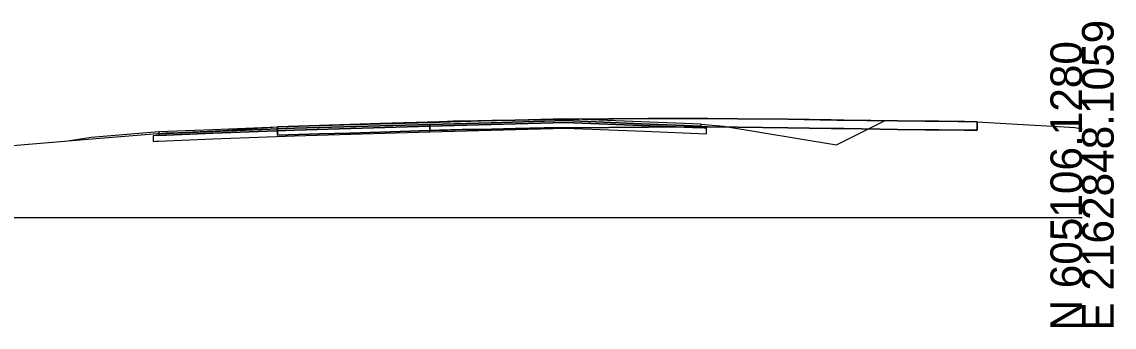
# Model space of a CAD drawing. Extents: x -26 to 1303, y -10 to 12038.
# Drawn here: x 206.1 to 302.8, y 9990.3 to 10017.3 of the extents above; entities that cross this region are included whole.
import ezdxf

# ---------------------------------------------------------------- set-up
doc = ezdxf.new("R2010")
doc.units = 0
for name, color, linetype in [('RD_GPK_XS_Cell', 7, 'Continuous'), ('RD_XS_Base', 7, 'Continuous'), ('RD_XS_ExGround', 7, 'Continuous'), ('RD_XS_ExPaveRet', 7, 'Continuous'), ('RD_XS_Greenside', 7, 'Continuous'), ('RD_XS_Pave', 7, 'Continuous'), ('RD_XS_PaveOvlay_CP', 7, 'Continuous'), ('RD_XS_TieSlope', 7, 'Continuous')]:
    doc.layers.add(name, color=color, linetype=linetype)

msp = doc.modelspace()

# ---------------------------------------------------------------- linework, layer by layer
at = {"layer": 'RD_GPK_XS_Cell'}
msp.add_line((150, 10000), (300, 10000), dxfattribs=at)
at = {"layer": 'RD_XS_Base'}
for p, q in [((242.262, 10008.146), (242.262, 10008.232)), ((242.262, 10008.232), (242.262, 10007.874)), ((247.684, 10008.225), (242.262, 10008.073)), ((242.262, 10008.073), (242.262, 10008.146)), ((254.263, 10008.41), (247.684, 10008.225)), ((260.954, 10008.142), (254.263, 10008.41)), ((266.263, 10007.93), (260.954, 10008.142)), ((218.003, 10007.246), (217.762, 10007.236)), ((217.762, 10007.236), (217.762, 10006.978)), ((218.262, 10007.256), (218.003, 10007.246)), ((223.047, 10007.448), (218.262, 10007.256)), ((230.262, 10007.737), (223.047, 10007.448)), ((223.047, 10006.948), (230.262, 10007.237)), ((242.262, 10008.073), (230.262, 10007.737)), ((230.262, 10007.237), (242.262, 10007.573)), ((242.262, 10008.073), (242.262, 10008.073)), ((242.262, 10008.073), (242.262, 10008.073)), ((242.262, 10007.801), (242.262, 10008.073)), ((242.262, 10007.874), (242.262, 10007.573)), ((242.262, 10007.573), (242.262, 10007.801)), ((242.262, 10007.573), (247.684, 10007.725)), ((247.684, 10007.725), (254.263, 10007.91)), ((254.263, 10007.91), (261.235, 10007.631)), ((261.235, 10007.631), (266.763, 10007.41)), ((266.544, 10007.919), (266.263, 10007.93)), ((266.763, 10007.91), (266.544, 10007.919)), ((266.763, 10007.629), (266.763, 10007.91)), ((266.763, 10007.41), (266.763, 10007.629)), ((217.762, 10006.978), (217.762, 10006.736)), ((217.762, 10006.736), (218.003, 10006.746)), ((218.003, 10006.746), (218.262, 10006.756)), ((218.262, 10006.756), (223.047, 10006.948))]:
    msp.add_line(p, q, dxfattribs=at)
at = {"layer": 'RD_XS_ExGround'}
msp.add_lwpolyline([(203.207, 10006.202), (207.088, 10006.507), (213.078, 10007.006), (218.879, 10007.501), (219.307, 10007.493), (223.898, 10007.688), (228.782, 10008.031), (232.493, 10008.146), (237.9, 10008.309), (243.81, 10008.49), (244.316, 10008.515), (244.522, 10008.52), (244.93, 10008.523), (245.804, 10008.523), (246.76, 10008.548), (252.362, 10008.677), (261.593, 10008.753), (266.863, 10008.772), (273.943, 10008.687), (278.287, 10008.621), (283.667, 10008.546), (287.328, 10008.51), (290.699, 10008.479), (294.248, 10008.249), (298.417, 10008.024), (299.355, 10007.972), (300, 10007.845)], dxfattribs=at)
at = {"layer": 'RD_XS_ExPaveRet'}
for points in [[(290.699, 10008.479), (290.7, 10008.479), (290.7, 10008.148), (290.7, 10007.729), (290.699, 10007.729), (290.699, 10007.729), (289.583, 10007.739), (287.328, 10007.76), (286.097, 10007.772), (283.667, 10007.796), (278.934, 10007.862), (278.287, 10007.871), (277.776, 10007.879), (273.943, 10007.937), (269.502, 10007.99), (266.863, 10008.022), (264.839, 10008.014), (261.593, 10008.003), (254.6, 10007.946), (252.362, 10007.927), (249.814, 10007.868), (247.742, 10007.82), (246.494, 10007.789), (245.838, 10007.774), (245.475, 10007.774), (245.118, 10007.774), (244.496, 10007.77), (244.414, 10007.767), (244.316, 10007.765), (244.074, 10007.753), (243.81, 10007.74), (243.073, 10007.717), (237.9, 10007.559), (235.183, 10007.477), (232.493, 10007.396), (230.658, 10007.339), (228.782, 10007.281), (228.782, 10007.771), (228.782, 10008.031), (230.658, 10008.089), (232.493, 10008.146), (235.183, 10008.227), (237.9, 10008.309), (243.073, 10008.467), (243.81, 10008.49), (244.074, 10008.503), (244.316, 10008.515), (244.414, 10008.517), (244.496, 10008.52), (245.118, 10008.524), (245.475, 10008.524), (245.838, 10008.524), (246.494, 10008.539), (247.742, 10008.57), (249.814, 10008.618), (252.362, 10008.677), (254.6, 10008.696), (261.593, 10008.753), (264.839, 10008.764), (266.863, 10008.772), (269.502, 10008.74), (273.943, 10008.687), (277.776, 10008.629), (278.287, 10008.621), (278.934, 10008.612), (283.667, 10008.546), (286.097, 10008.522), (287.328, 10008.51), (289.583, 10008.489), (290.699, 10008.479), (290.699, 10008.479)], [(290.699, 10008.479), (289.583, 10008.489), (287.328, 10008.51), (286.097, 10008.522), (283.667, 10008.546), (278.934, 10008.612), (278.287, 10008.621), (277.776, 10008.629), (273.943, 10008.687), (269.502, 10008.74), (266.863, 10008.772), (264.839, 10008.764), (261.593, 10008.753), (254.6, 10008.696), (252.362, 10008.677), (249.814, 10008.618), (247.742, 10008.57), (246.494, 10008.539), (245.838, 10008.524), (245.475, 10008.524), (245.118, 10008.524), (244.496, 10008.52), (244.414, 10008.517), (244.316, 10008.515), (244.074, 10008.503), (243.81, 10008.49), (243.073, 10008.467), (237.9, 10008.309), (235.183, 10008.227), (232.493, 10008.146), (230.658, 10008.089), (228.782, 10008.031), (228.782, 10007.771), (228.782, 10007.281), (230.658, 10007.339), (232.493, 10007.396), (235.183, 10007.477), (237.9, 10007.559), (243.073, 10007.717), (243.81, 10007.74), (244.074, 10007.753), (244.316, 10007.765), (244.414, 10007.767), (244.496, 10007.77), (245.118, 10007.774), (245.475, 10007.774), (245.838, 10007.774), (246.494, 10007.789), (247.742, 10007.82), (249.814, 10007.868), (252.362, 10007.927), (254.6, 10007.946), (261.593, 10008.003), (264.839, 10008.014), (266.863, 10008.022), (269.502, 10007.99), (273.943, 10007.937), (277.776, 10007.879), (278.287, 10007.871), (278.934, 10007.862), (283.667, 10007.796), (286.097, 10007.772), (287.328, 10007.76), (289.583, 10007.739), (290.699, 10007.729), (290.7, 10007.729), (290.7, 10008.148), (290.699, 10008.479), (290.699, 10008.479)]]:
    msp.add_lwpolyline(points, dxfattribs=at)
at = {"layer": 'RD_XS_Greenside'}
for p, q in [((278.264, 10006.422), (282.562, 10008.571)), ((268.263, 10008.088), (278.264, 10006.422)), ((212.262, 10007.094), (210.392, 10006.782))]:
    msp.add_line(p, q, dxfattribs=at)
at = {"layer": 'RD_XS_Pave'}
for p, q in [((242.262, 10008.391), (230.262, 10008.055)), ((242.262, 10008.232), (230.262, 10007.896)), ((230.262, 10007.896), (242.262, 10008.232)), ((247.684, 10008.543), (242.262, 10008.391)), ((247.684, 10008.384), (242.262, 10008.232)), ((242.262, 10008.232), (247.684, 10008.384)), ((242.262, 10008.146), (242.262, 10008.232)), ((242.262, 10008.232), (242.262, 10008.232)), ((242.262, 10008.232), (242.262, 10008.232)), ((242.262, 10008.232), (242.262, 10008.146)), ((242.262, 10008.073), (247.684, 10008.225)), ((242.262, 10008.073), (242.262, 10008.146)), ((242.262, 10008.146), (242.262, 10008.073)), ((254.263, 10008.728), (247.684, 10008.543)), ((254.263, 10008.569), (247.684, 10008.384)), ((247.684, 10008.384), (254.263, 10008.569)), ((247.684, 10008.225), (254.263, 10008.41)), ((260.954, 10008.46), (254.263, 10008.728)), ((260.954, 10008.301), (254.263, 10008.569)), ((254.263, 10008.569), (260.954, 10008.301)), ((254.263, 10008.41), (260.954, 10008.142)), ((266.263, 10008.248), (260.954, 10008.46)), ((266.263, 10008.089), (260.954, 10008.301)), ((260.954, 10008.301), (266.263, 10008.089)), ((260.954, 10008.142), (266.263, 10007.93)), ((266.263, 10008.159), (266.263, 10008.248)), ((266.263, 10008.089), (266.263, 10008.159)), ((223.047, 10007.766), (218.262, 10007.574)), ((223.047, 10007.607), (218.262, 10007.415)), ((218.262, 10007.415), (223.047, 10007.607)), ((218.262, 10007.574), (218.262, 10007.492)), ((218.262, 10007.492), (218.262, 10007.415)), ((218.262, 10007.256), (223.047, 10007.448)), ((218.262, 10007.415), (218.262, 10007.333)), ((218.262, 10007.333), (218.262, 10007.256)), ((230.262, 10008.055), (223.047, 10007.766)), ((230.262, 10007.896), (223.047, 10007.607)), ((223.047, 10007.607), (230.262, 10007.896)), ((223.047, 10007.448), (230.262, 10007.737)), ((230.262, 10007.737), (242.262, 10008.073)), ((242.262, 10008.073), (242.262, 10008.073)), ((242.262, 10008.073), (242.262, 10008.073)), ((266.263, 10008), (266.263, 10008.089)), ((266.263, 10007.93), (266.263, 10008))]:
    msp.add_line(p, q, dxfattribs=at)
at = {"layer": 'RD_XS_PaveOvlay_CP'}
for p, q in [((242.262, 10008.391), (230.262, 10008.055)), ((247.684, 10008.543), (242.262, 10008.391)), ((254.263, 10008.728), (247.684, 10008.543)), ((260.954, 10008.46), (254.263, 10008.728)), ((266.263, 10008.248), (260.954, 10008.46)), ((223.047, 10007.766), (218.262, 10007.574)), ((230.262, 10008.055), (223.047, 10007.766))]:
    msp.add_line(p, q, dxfattribs=at)
at = {"layer": 'RD_XS_TieSlope'}
for p, q in [((266.263, 10008.248), (268.263, 10008.088)), ((218.262, 10007.574), (212.262, 10007.094))]:
    msp.add_line(p, q, dxfattribs=at)

# ---------------------------------------------------------------- texts
at = {"layer": 'RD_GPK_XS_Cell'}
for s, p in [('E 2162848.1059', (302.8, 9990)), ('N 605106.1280', (300, 9990))]:
    msp.add_text(s, height=2.8, rotation=90, dxfattribs=at).set_placement(p)

doc.saveas('drawing.dxf')
